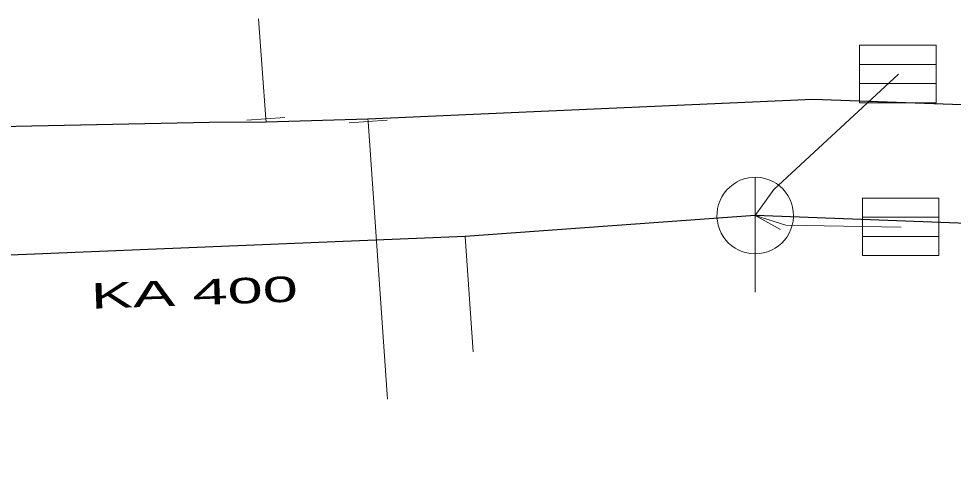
# Model space of a CAD drawing. Extents: x -688432 to -687974, y -973332 to -972704.
# Drawn here: x -688121.48 to -688097.06, y -972935.52 to -972923.6 of the extents above; entities that cross this region are included whole.
import ezdxf
from ezdxf.enums import TextEntityAlignment as Align

# ---------------------------------------------------------------- set-up
doc = ezdxf.new("R2010")
doc.units = 0
doc.header["$LTSCALE"] = 0.27
for name, color, linetype, lineweight in [('1', 7, 'Continuous', 25), ('11', 7, 'Continuous', 13), ('13', 7, 'Continuous', 13), ('14', 7, 'Continuous', 25), ('17', 7, 'Continuous', 25), ('22', 7, 'Continuous', 13), ('34', 7, 'Continuous', 13)]:
    doc.layers.add(name, color=color, linetype=linetype, lineweight=lineweight)

msp = doc.modelspace()

# ---------------------------------------------------------------- linework, layer by layer
at = {"layer": '11'}
for p, q in [((-688101.579, -972929.1), (-688102.239, -972928.739)), ((-688109.609, -972932.3), (-688109.82, -972929.289))]:
    msp.add_line(p, q, dxfattribs=at)
for points in [[(-688098.5, -972925.05), (-688101.75, -972928.059), (-688102.239, -972928.739)], [(-688098.43, -972929.039), (-688101.44, -972928.989), (-688102.239, -972928.739)]]:
    msp.add_lwpolyline(points, dxfattribs=at)
at = {"layer": '13'}
for p, q in [((-688115.025, -972926.214), (-688115.219, -972923.6)), ((-688112.354, -972926.288), (-688111.85, -972933.53))]:
    msp.add_line(p, q, dxfattribs=at)
at = {"layer": '14', "lineweight": 13}
for p, q in [((-688115.02, -972926.289), (-688115.025, -972926.214)), ((-688112.359, -972926.21), (-688112.354, -972926.288))]:
    msp.add_line(p, q, dxfattribs=at)
at = {"layer": '14'}
for points in [[(-688102.239, -972928.739), (-688109.82, -972929.289), (-688124.05, -972929.87)], [(-688082.32, -972929.62), (-688084.92, -972929.39), (-688102.239, -972928.739)]]:
    msp.add_lwpolyline(points, dxfattribs=at)
at = {"layer": '17'}
msp.add_lwpolyline([(-688142.539, -972926.989), (-688136.969, -972927.03), (-688124.52, -972926.469), (-688116.5, -972926.3), (-688115.02, -972926.289), (-688112.359, -972926.21), (-688100.73, -972925.699), (-688087.609, -972926.17), (-688083.969, -972927.539), (-688080.94, -972929.1), (-688078.329, -972931.09), (-688076.37, -972933.14), (-688074.449, -972935.62), (-688070.85, -972940.129), (-688068.85, -972942.57), (-688067.02, -972944.8), (-688063.62, -972948.98), (-688063.329, -972949.34), (-688059.6, -972954.02), (-688058.039, -972955.829), (-688055.76, -972958.48), (-688051.969, -972962.76), (-688050.239, -972964.93)], dxfattribs=at)
at = {"layer": '22'}
for p, q in [((-688099.511, -972924.793), (-688097.511, -972924.793)), ((-688099.511, -972925.293), (-688097.511, -972925.293)), ((-688102.239, -972930.739), (-688102.238, -972927.739)), ((-688099.441, -972928.782), (-688097.441, -972928.782)), ((-688099.441, -972929.282), (-688097.441, -972929.282))]:
    msp.add_line(p, q, dxfattribs=at)
for points in [[(-688099.511, -972924.293), (-688097.511, -972924.293), (-688097.511, -972925.793), (-688099.511, -972925.793)], [(-688101.239, -972928.739), (-688101.244, -972928.63), (-688101.262, -972928.522), (-688101.292, -972928.416), (-688101.332, -972928.315), (-688101.384, -972928.218), (-688101.446, -972928.128), (-688101.518, -972928.045), (-688101.598, -972927.971), (-688101.686, -972927.905), (-688101.78, -972927.85), (-688101.88, -972927.805), (-688101.985, -972927.772), (-688102.092, -972927.75), (-688102.201, -972927.74), (-688102.311, -972927.742), (-688102.419, -972927.756), (-688102.526, -972927.781), (-688102.629, -972927.818), (-688102.727, -972927.867), (-688102.819, -972927.925), (-688102.905, -972927.994), (-688102.982, -972928.071), (-688103.051, -972928.157), (-688103.11, -972928.249), (-688103.158, -972928.347), (-688103.195, -972928.45), (-688103.221, -972928.557), (-688103.235, -972928.665), (-688103.238, -972928.775), (-688103.228, -972928.884), (-688103.207, -972928.991), (-688103.173, -972929.095), (-688103.129, -972929.195), (-688103.074, -972929.29), (-688103.008, -972929.378), (-688102.934, -972929.458), (-688102.851, -972929.53), (-688102.761, -972929.592), (-688102.665, -972929.644), (-688102.563, -972929.685), (-688102.458, -972929.715), (-688102.35, -972929.733), (-688102.24, -972929.739), (-688102.131, -972929.733), (-688102.023, -972929.715), (-688101.918, -972929.686), (-688101.816, -972929.645), (-688101.719, -972929.593), (-688101.629, -972929.531), (-688101.546, -972929.46), (-688101.471, -972929.38), (-688101.406, -972929.292), (-688101.35, -972929.198), (-688101.306, -972929.098), (-688101.272, -972928.994), (-688101.25, -972928.886), (-688101.24, -972928.777)], [(-688099.441, -972928.282), (-688097.441, -972928.282), (-688097.441, -972929.782), (-688099.441, -972929.782)]]:
    msp.add_lwpolyline(points, close=True, dxfattribs=at)
at = {"layer": '34'}
for p, q in [((-688115.523, -972926.251), (-688114.526, -972926.177)), ((-688111.855, -972926.253), (-688112.852, -972926.321))]:
    msp.add_line(p, q, dxfattribs=at)

# ---------------------------------------------------------------- texts
at = {"layer": '1', "width": 1.85}
msp.add_text('KA 400', height=0.6667, rotation=2, dxfattribs=at).set_placement((-688116.8826, -972931.0787), align=Align.CENTER)
msp.add_text('KA 400', height=0.6667, rotation=2, dxfattribs=at).set_placement((-688116.8826, -972931.0787), align=Align.CENTER)
msp.add_text('KA 400', height=0.6667, rotation=2, dxfattribs=at).set_placement((-688116.8826, -972931.0787), align=Align.CENTER)
msp.add_text('KA 400', height=0.6667, rotation=2, dxfattribs=at).set_placement((-688116.8826, -972931.0787), align=Align.CENTER)
msp.add_text('KA 400', height=0.6667, rotation=2, dxfattribs=at).set_placement((-688116.8826, -972931.0787), align=Align.CENTER)

doc.saveas('drawing.dxf')
